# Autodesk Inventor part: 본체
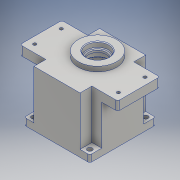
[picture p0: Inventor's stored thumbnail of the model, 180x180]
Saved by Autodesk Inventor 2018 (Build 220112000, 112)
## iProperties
Created: 2020-07
Part Number: 본체
Material: 알루미늄 6061
Document SubType Name: Modeling
Designer: Admin
Density: 2.7 g/cm^3
Appearance: 알루미늄 - 평지
Mass: 848.197 g
Surface Area: 818.869 cm^2
Volume: 314.147 cm^3
Author: Admin
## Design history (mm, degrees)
sketch "스케치4"
  geometry: L1 (-47, -47)-(47, -47); L2 (47, -47)-(47, 47); L3 (47, 47)-(-47, 47); L4 (-47, 47)-(-47, -47); L5 (-47, -47)-(47, 47); L6 (47, -47)-(-47, 47); 1 further point
  constraints: 12 end point, 2 midpoint, 2 parallel, 1 horizontal, 1 perpendicular
  dimensions: "d15" = 94 distance of L3.end L2.end; "d16" = 94 distance of L3.end L1.start
extrude "돌출4" new body sketch "스케치4" distance "d17" = 67; taper "d18" = 0 deg
sketch "스케치5"
  geometry: L1 (-70, -47)-(70, -47); L2 (70, -47)-(70, 47); L3 (70, 47)-(-70, 47); L4 (-70, 47)-(-70, -47); L5 (-70, -47)-(70, 47); L6 (70, -47)-(-70, 47); 1 further point
  constraints: 12 end point, 2 midpoint, 2 parallel, 1 horizontal, 1 perpendicular
  dimensions: "d19" = 94 distance between parallel lines of L1 L3; "d20" = 140 distance between parallel lines of L4 L2
extrude "돌출5" join sketch "스케치5" distance "d21" = 13; taper "d22" = 0 deg
sketch "스케치6"
  geometry: L1 (70, 47)-(33, 47); L2 (33, 47)-(33, 30); L3 (33, 30)-(70, 30); L4 (70, 30)-(70, 47); L5 (70, -47)-(70, 47) reference; L6 (70, 47)-(-70, 47) reference; 1 further point
  constraints: 8 end point, 2 parallel, 1 horizontal, 1 perpendicular
  dimensions: "d23" = 37 distance of L1.start L1.end; "d24" = 17 distance of L3.end L1.start; "d25" = 0 distance between parallel lines of L5 L4; "d26" = 0 distance between parallel lines of L6 L1
extrude "돌출6" cut sketch "스케치6" distance "d27" = 70; taper "d28" = 0 deg
sketch "스케치7"
  geometry: C1 r 27.5 at (0, 11); 1 further point
  constraints: 1 centre point
  dimensions: "d29" = 11 distance of point (0, 0) C1.centre; "d30" = 55 diameter of C1
extrude "돌출7" join sketch "스케치7" distance "d31" = 7; taper "d32" = 0 deg
sketch "스케치8"
  geometry: C1 r 16 at (0, 0); 1 further point
  constraints: 1 centre point
  dimensions: "d33" = 32 diameter of C1
extrude "돌출8" cut sketch "스케치8" distance "d34" = 8.3; taper "d35" = 0 deg
sketch "스케치9"
  geometry: C1 r 12.5 at (0, 0); 1 further point
  constraints: 1 centre point
  dimensions: "d36" = 25 diameter of C1
extrude "돌출9" cut sketch "스케치9" distance "d37" = 4.7; taper "d38" = 0 deg
sketch "스케치10"
  geometry: C1 r 43 at (0, 0); 1 further point
  constraints: 1 centre point, 1 coincident
  dimensions: "d39" = 86 diameter of C1
extrude "돌출10" cut sketch "스케치10" distance "d40" = 9; taper "d41" = 0 deg
sketch "스케치11"
  geometry: C1 r 40 at (0, 0); 1 further point
  constraints: 1 centre point, 1 coincident
  dimensions: "d42" = 80 diameter of C1
extrude "돌출11" cut sketch "스케치11" distance "d43" = 64; taper "d44" = 0 deg
sketch "스케치12"
  geometry: L1 (98, 0)-(-98, 0) reference; A1 r 21 centre (0, 11) between (8.978, -7.984) and (-8.978, -7.984); A2 r 15 centre (0, -20) between (-8.978, -7.984) and (8.978, -7.984); 1 further point
  constraints: 4 point on circle, 2 centre point
  dimensions: "d45" = 11 distance of point (0, 0) A1.centre; "d46" = 20 distance from line of A2.centre L1; "d47" = 42 diameter of A1; "d48" = 30 diameter of A2
extrude "돌출12" join sketch "스케치12" distance "d49" = 7; taper "d50" = 0 deg
sketch "스케치13"
  geometry: L1 (33, 47)-(33, 30) reference; L2 (33, 30)-(47, 30) reference; L3 (47, 30)-(47, -30) reference; L4 (47, -30)-(33, -30) reference; L5 (33, -30)-(33, -47) reference; L6 (33, -47)-(-33, -47) reference; L7 (-33, -47)-(-33, -30) reference; L8 (-33, -30)-(-47, -30) reference; L9 (-47, -30)-(-47, 30) reference; L10 (-47, 30)-(-33, 30) reference; L11 (-33, 30)-(-33, 47) reference; L12 (-33, 47)-(33, 47) reference; C1 r 40 at (0, 0) reference; C2 r 17.5 at (0, 11); C3 r 11 at (0, -20); A1 r 21 centre (0, 11) between (8.978, -7.984) and (-8.978, -7.984) reference; A2 r 15 centre (0, -20) between (-8.978, -7.984) and (8.978, -7.984) reference; 1 further point
  constraints: 2 centre point, 2 coincident
  dimensions: "d51" = 35 diameter of C2; "d52" = 22 diameter of C3
extrude "돌출13" cut sketch "스케치13" distance "d53" = 10; taper "d54" = 0 deg
sketch "스케치14"
  geometry: L1 (33, 47)-(33, 30) reference; L2 (33, 30)-(47, 30) reference; L3 (47, 30)-(47, -30) reference; L4 (47, -30)-(33, -30) reference; L5 (33, -30)-(33, -47) reference; L6 (33, -47)-(-33, -47) reference; L7 (-33, -47)-(-33, -30) reference; L8 (-33, -30)-(-47, -30) reference; L9 (-47, -30)-(-47, 30) reference; L10 (-47, 30)-(-33, 30) reference; L11 (-33, 30)-(-33, 47) reference; L12 (-33, 47)-(33, 47) reference; C1 r 17.5 at (0, 11) reference; C2 r 40 at (0, 0) reference; C3 r 11 at (0, -20); A1 r 21 centre (0, 11) between (8.978, -7.984) and (-8.978, -7.984) reference; A2 r 15 centre (0, -20) between (-8.978, -7.984) and (8.978, -7.984) reference; 1 further point
  constraints: 1 centre point, 1 coincident
  dimensions: "d55" = 22 diameter of C3
extrude "돌출14" cut sketch "스케치14" distance "d56" = 7; taper "d57" = 0 deg
sketch "스케치15"
  geometry: L1 (33, 67)-(33, 50) reference; L2 (33, 50)-(70, 50) reference; L3 (70, 50)-(70, -10) reference; L4 (70, -10)-(33, -10) reference; L5 (33, -10)-(33, -27) reference; L6 (33, -27)-(-33, -27) reference; L7 (-33, -27)-(-33, -10) reference; L8 (-33, -10)-(-70, -10) reference; L9 (-70, -10)-(-70, 50) reference; L10 (-70, 50)-(-33, 50) reference; L11 (-33, 50)-(-33, 67) reference; L12 (-33, 67)-(33, 67) reference; C1 r 11 at (0, 0) reference; C2 r 17.5 at (0, 31) reference; C3 r 40 at (0, 20) reference; C4 r 9.5 at (0, 0); A1 r 21 centre (0, 31) between (8.978, 12.016) and (-8.978, 12.016) reference; A2 r 15 centre (0, 0) between (-8.978, 12.016) and (8.978, 12.016) reference; 1 further point
  constraints: 1 centre point, 1 coincident
  dimensions: "d58" = 19 diameter of C4
extrude "돌출15" cut sketch "스케치15" distance "d59" = 3; taper "d60" = 0 deg
sketch "스케치21"
  geometry: L1 (-80, 60)-(-80, 77) reference; L2 (-80, 77)-(-66, 77) reference; C1 r 3.5 at (-73, 70); C2 r 3.5 at (-73, -10); 1 further point
  constraints: 2 centre point, 1 vertical alignment
  dimensions: "d67" = 7 diameter of C1; "d68" = 7 diameter of C2; "d69" = 80 distance of C1.centre C2.centre; "d70" = 7 distance from line of C1.centre L1; "d71" = 7 distance from line of C1.centre L2
extrude "돌출16" cut sketch "스케치21" extent not by distance; stored distance "d72" = 3; taper "d73" = 0 deg
sketch "스케치23"
  geometry: L1 (98, 0)-(-98, 0) reference; L2 (-70, -30)-(-70, 30) reference; 3 further points
  constraints: 1 symmetric about line
  dimensions: "d76" = 38 distance of point (-60, -19) point (-60, 19); "d77" = 10 distance from line of point (-60, 19) L2
hole "구멍1" sketch "스케치23" at (-60, 19), (-60, -19) diameter "d78" = 4.5; stored, may be unused: countersink angle "d82" = 90 deg, drill point angle "d84" = 118 deg; dims "d79" = 6.35, "d80" = 10, "d81" = 5, "d83" = 9.525
fillet "모깎기1" dims "d96" = 3
chamfer "모따기1" distance "d97" = 1; stored, may be unused: second distance "d98" = 2, angle "d99" = 45 deg
chamfer "모따기2" distance "d100" = 1; stored, may be unused: second distance "d101" = 2, angle "d102" = 45 deg
chamfer "모따기3" distance "d103" = 1; stored, may be unused: second distance "d104" = 2, angle "d105" = 45 deg
fillet "모깎기2" dims "d106" = 3
sketch "스케치28"
  geometry: L1 (11, 80)-(-77, 80) reference; 3 further points
  constraints: 1 midpoint, 1 vertical alignment, 1 other
  dimensions: "d107" = 40 distance of point (-33, 80) point (-33, 40)
feature "엠보싱1" sketch "스케치28" dims "d15" = 94, "d16" = 94, "d23" = 37, "d24" = 17, "d25" = 0, "d26" = 0, "d108" = 0.5, "d109" = 0
sketch "스케치29" dims "d110" = 72
  geometry: C1 r 4 at (-36, 0); 2 further points
  constraints: 1 centre point, 1 coincident, 1 horizontal alignment, 2 other
  dimensions: "d111" = 8 diameter of C1
extrude "돌출18" join sketch "스케치29" stored distance "d112" = 10; taper "d113" = 0 deg
sketch "스케치32"
  geometry: 2 further points
hole "구멍2" sketch "스케치32" at (0, 0) diameter "d114" = 3.242; stored, may be unused: countersink angle "d118" = 90 deg, drill point angle "d120" = 118 deg; dims "d115" = 7, "d116" = 4, "d117" = 2, "d119" = 9
node "솔리드2"
mirror "미러3"
mirror "미러4"
mirror "미러5"
mirror "미러6"
mirror "미러7"
mirror "미러8"
node "절단 모서리 투영1"
node "절단 모서리 투영2"
node "절단 모서리 투영3"
